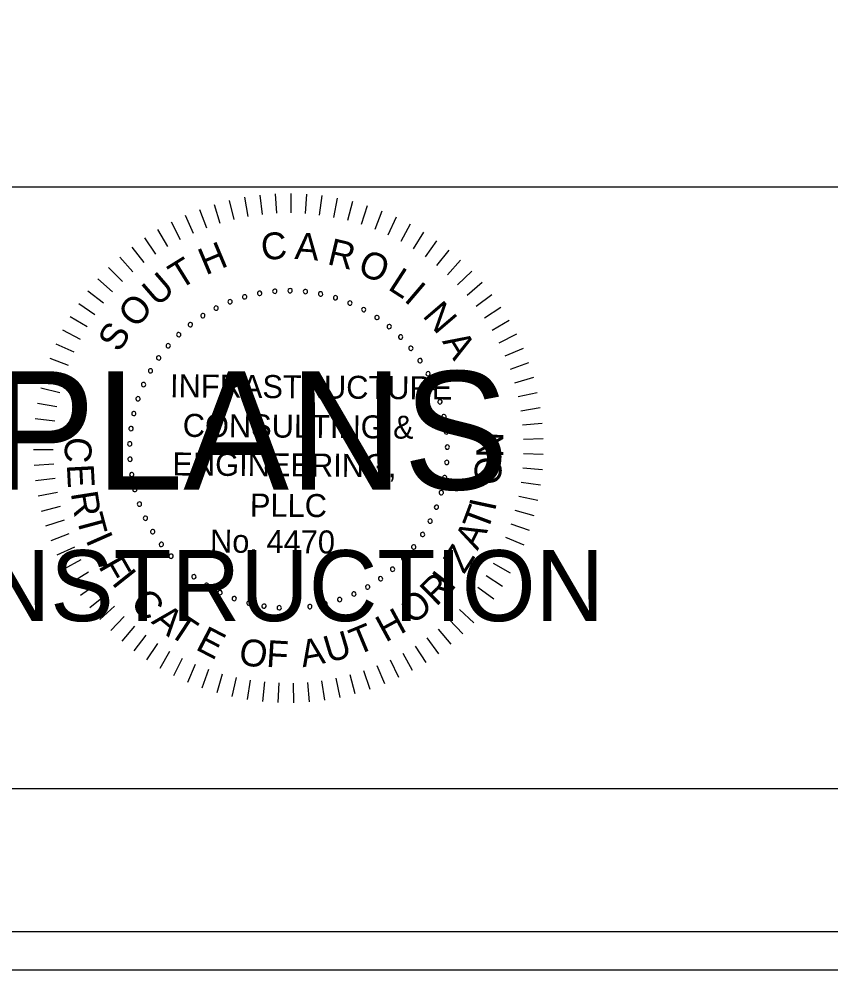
# Model space of a CAD drawing. Extents: x 967 to 1746, y 964 to 7904.
# Drawn here: x 1189.3 to 1212.88, y 6003.72 to 6031.36 of the extents above; entities that cross this region are included whole.
import ezdxf

# ---------------------------------------------------------------- set-up
doc = ezdxf.new("R2010")
doc.units = 0
for name, color, linetype in [('RD_SHT_Bndy', 7, 'Continuous'), ('RD_SHT_IplotShp', 7, 'Continuous'), ('RD_SHT_Misc1', 7, 'Continuous'), ('RD_SHT_Misc2', 7, 'Continuous'), ('RD_Sketch1', 7, 'Continuous')]:
    doc.layers.add(name, color=color, linetype=linetype)

msp = doc.modelspace()

# ---------------------------------------------------------------- linework, layer by layer
at = {"layer": 'RD_SHT_Bndy'}
for p, q in [((996.114, 6026.486), (1323.886, 6026.486)), ((1323.886, 6008.983), (996.114, 6008.983))]:
    msp.add_line(p, q, dxfattribs=at)
at = {"layer": 'RD_SHT_IplotShp'}
for points in [[(967.409, 6003.72), (1326.285, 6003.72), (1326.285, 6223.72), (967.409, 6223.72)], [(988.525, 6004.84), (1326.285, 6004.84), (1326.285, 6222.6), (988.525, 6222.6)]]:
    msp.add_lwpolyline(points, close=True, dxfattribs=at)
at = {"layer": 'RD_SHT_Misc1'}
for p, q in [((1195.403, 6026.09), (1195.536, 6025.536)), ((1195.846, 6026.181), (1195.945, 6025.62)), ((1196.292, 6026.245), (1196.357, 6025.68)), ((1196.742, 6026.282), (1196.772, 6025.714)), ((1197.194, 6026.292), (1197.189, 6025.723)), ((1197.645, 6026.274), (1197.606, 6025.706)), ((1198.094, 6026.228), (1198.02, 6025.664)), ((1198.54, 6026.156), (1198.432, 6025.596)), ((1198.98, 6026.056), (1198.838, 6025.504)), ((1194.54, 6025.827), (1194.739, 6025.293)), ((1194.968, 6025.971), (1195.134, 6025.427)), ((1199.414, 6025.929), (1199.238, 6025.387)), ((1199.839, 6025.777), (1199.63, 6025.246)), ((1194.122, 6025.656), (1194.353, 6025.136)), ((1200.253, 6025.598), (1200.013, 6025.082)), ((1193.321, 6025.241), (1193.614, 6024.752)), ((1193.715, 6025.461), (1193.978, 6024.956)), ((1200.656, 6025.395), (1200.385, 6024.894)), ((1192.94, 6024.997), (1193.263, 6024.528)), ((1201.047, 6025.167), (1200.745, 6024.684)), ((1201.422, 6024.917), (1201.092, 6024.453)), ((1192.576, 6024.731), (1192.926, 6024.282)), ((1201.781, 6024.643), (1201.424, 6024.2)), ((1192.228, 6024.443), (1192.605, 6024.016)), ((1191.899, 6024.134), (1192.301, 6023.731)), ((1202.124, 6024.349), (1201.739, 6023.928)), ((1202.447, 6024.034), (1202.038, 6023.638)), ((1191.589, 6023.805), (1192.015, 6023.428)), ((1202.751, 6023.7), (1202.318, 6023.329)), ((1191.299, 6023.459), (1191.748, 6023.108)), ((1203.034, 6023.348), (1202.579, 6023.004)), ((1191.032, 6023.095), (1191.501, 6022.772)), ((1190.787, 6022.716), (1191.274, 6022.422)), ((1203.294, 6022.979), (1202.82, 6022.664)), ((1203.532, 6022.595), (1203.04, 6022.31)), ((1190.565, 6022.323), (1191.07, 6022.059)), ((1203.746, 6022.198), (1203.237, 6021.943)), ((1190.368, 6021.916), (1190.888, 6021.684)), ((1203.936, 6021.788), (1203.412, 6021.564)), ((1190.196, 6021.499), (1190.729, 6021.299)), ((1204.1, 6021.367), (1203.563, 6021.176)), ((1190.05, 6021.072), (1190.594, 6020.905)), ((1204.238, 6020.937), (1203.691, 6020.779)), ((1189.93, 6020.636), (1190.484, 6020.503)), ((1204.349, 6020.5), (1203.794, 6020.375)), ((1189.837, 6020.195), (1190.398, 6020.095)), ((1204.434, 6020.056), (1203.872, 6019.966)), ((1189.771, 6019.748), (1190.337, 6019.683)), ((1204.491, 6019.608), (1203.925, 6019.552)), ((1189.732, 6019.298), (1190.301, 6019.267)), ((1204.522, 6019.158), (1203.953, 6019.137)), ((1189.721, 6018.847), (1190.29, 6018.851)), ((1204.524, 6018.706), (1203.955, 6018.72)), ((1189.737, 6018.396), (1190.306, 6018.434)), ((1204.499, 6018.256), (1203.932, 6018.304)), ((1189.781, 6017.946), (1190.346, 6018.019)), ((1204.447, 6017.807), (1203.884, 6017.89)), ((1189.852, 6017.5), (1190.412, 6017.608)), ((1204.367, 6017.363), (1203.81, 6017.479)), ((1189.951, 6017.06), (1190.502, 6017.201)), ((1204.261, 6016.924), (1203.712, 6017.074)), ((1190.076, 6016.626), (1190.617, 6016.8)), ((1204.128, 6016.492), (1203.589, 6016.676)), ((1190.227, 6016.2), (1190.757, 6016.408)), ((1203.969, 6016.07), (1203.442, 6016.286)), ((1190.403, 6015.785), (1190.92, 6016.024)), ((1203.784, 6015.658), (1203.271, 6015.906)), ((1190.605, 6015.381), (1191.106, 6015.651)), ((1203.574, 6015.258), (1203.078, 6015.537)), ((1190.831, 6014.99), (1191.315, 6015.291)), ((1203.341, 6014.871), (1202.862, 6015.18)), ((1191.081, 6014.614), (1191.545, 6014.943)), ((1203.085, 6014.5), (1202.626, 6014.837)), ((1191.353, 6014.253), (1191.796, 6014.61)), ((1202.806, 6014.145), (1202.368, 6014.509)), ((1191.646, 6013.91), (1192.067, 6014.293)), ((1202.506, 6013.807), (1202.092, 6014.197)), ((1191.96, 6013.585), (1192.356, 6013.994)), ((1202.186, 6013.488), (1201.796, 6013.903)), ((1192.293, 6013.28), (1192.664, 6013.712)), ((1201.847, 6013.19), (1201.484, 6013.628)), ((1192.644, 6012.996), (1192.988, 6013.45)), ((1201.491, 6012.912), (1201.155, 6013.372)), ((1193.011, 6012.734), (1193.327, 6013.208)), ((1201.119, 6012.657), (1200.811, 6013.136)), ((1193.394, 6012.495), (1193.68, 6012.987)), ((1193.791, 6012.279), (1194.047, 6012.788)), ((1200.731, 6012.425), (1200.453, 6012.922)), ((1194.2, 6012.088), (1194.424, 6012.612)), ((1199.918, 6012.034), (1199.702, 6012.561)), ((1200.331, 6012.217), (1200.083, 6012.73)), ((1194.62, 6011.923), (1194.812, 6012.459)), ((1195.05, 6011.783), (1195.208, 6012.33)), ((1195.487, 6011.67), (1195.612, 6012.225)), ((1199.063, 6011.745), (1198.913, 6012.295)), ((1199.495, 6011.877), (1199.312, 6012.416)), ((1195.93, 6011.584), (1196.021, 6012.146)), ((1196.377, 6011.524), (1196.434, 6012.091)), ((1196.828, 6011.493), (1196.85, 6012.062)), ((1197.279, 6011.488), (1197.267, 6012.058)), ((1197.73, 6011.512), (1197.683, 6012.079)), ((1198.179, 6011.562), (1198.097, 6012.126)), ((1198.624, 6011.64), (1198.508, 6012.198))]:
    msp.add_line(p, q, dxfattribs=at)
for centre, start, end in [((1195.851, 6023.285), 16.1422, 196.1422), ((1195.851, 6023.285), 196.1422, 16.1422), ((1196.285, 6023.388), 10.6038, 190.6038), ((1196.285, 6023.388), 190.6038, 10.6038), ((1196.727, 6023.447), 5.0653, 185.0653), ((1196.727, 6023.447), 185.0653, 5.0653), ((1197.172, 6023.464), 359.5268, 179.5268), ((1197.172, 6023.464), 179.5268, 359.5268), ((1197.617, 6023.438), 173.9884, 353.9884), ((1197.617, 6023.438), 353.9884, 173.9884), ((1198.057, 6023.369), 168.4499, 348.4499), ((1198.057, 6023.369), 348.4499, 168.4499), ((1198.489, 6023.258), 162.9114, 342.9114), ((1198.489, 6023.258), 342.9114, 162.9114), ((1195.023, 6022.958), 27.2191, 207.2191), ((1195.023, 6022.958), 207.2191, 27.2191), ((1195.429, 6023.142), 21.6807, 201.6807), ((1195.429, 6023.142), 201.6807, 21.6807), ((1198.908, 6023.106), 157.373, 337.373), ((1198.908, 6023.106), 337.373, 157.373), ((1194.637, 6022.736), 32.7576, 212.7576), ((1194.637, 6022.736), 212.7576, 32.7576), ((1199.31, 6022.914), 151.8345, 331.8345), ((1199.31, 6022.914), 331.8345, 151.8345), ((1199.692, 6022.684), 146.2961, 326.2961), ((1199.692, 6022.684), 326.2961, 146.2961), ((1194.274, 6022.478), 38.2961, 218.2961), ((1194.274, 6022.478), 218.2961, 38.2961), ((1200.05, 6022.419), 140.7576, 320.7576), ((1200.05, 6022.419), 320.7576, 140.7576), ((1193.937, 6022.186), 43.8345, 223.8345), ((1193.937, 6022.186), 223.8345, 43.8345), ((1200.38, 6022.12), 135.2191, 315.2191), ((1200.38, 6022.12), 315.2191, 135.2191), ((1193.63, 6021.862), 49.373, 229.373), ((1193.63, 6021.862), 229.373, 49.373), ((1200.68, 6021.79), 129.6807, 309.6807), ((1200.68, 6021.79), 309.6807, 129.6807), ((1193.356, 6021.511), 54.9114, 234.9114), ((1193.356, 6021.511), 234.9114, 54.9114), ((1200.947, 6021.433), 124.1422, 304.1422), ((1200.947, 6021.433), 304.1422, 124.1422), ((1193.117, 6021.135), 60.4499, 240.4499), ((1193.117, 6021.135), 240.4499, 60.4499), ((1201.179, 6021.052), 118.6038, 298.6038), ((1201.179, 6021.052), 298.6038, 118.6038), ((1192.915, 6020.737), 65.9884, 245.9884), ((1192.915, 6020.737), 245.9884, 65.9884), ((1201.372, 6020.651), 113.0653, 293.0653), ((1201.372, 6020.651), 293.0653, 113.0653), ((1192.753, 6020.322), 71.5268, 251.5268), ((1192.753, 6020.322), 251.5268, 71.5268), ((1201.526, 6020.233), 107.5268, 287.5268), ((1201.526, 6020.233), 287.5268, 107.5268), ((1192.632, 6019.894), 77.0653, 257.0653), ((1192.632, 6019.894), 257.0653, 77.0653), ((1201.638, 6019.801), 101.9884, 281.9884), ((1201.638, 6019.801), 281.9884, 101.9884), ((1192.552, 6019.455), 82.6038, 262.6038), ((1192.552, 6019.455), 262.6038, 82.6038), ((1201.709, 6019.361), 96.4499, 276.4499), ((1201.709, 6019.361), 276.4499, 96.4499), ((1192.515, 6019.011), 88.1422, 268.1422), ((1192.515, 6019.011), 268.1422, 88.1422), ((1201.737, 6018.917), 90.9114, 270.9114), ((1201.737, 6018.917), 270.9114, 90.9114), ((1192.522, 6018.565), 93.6807, 273.6807), ((1192.522, 6018.565), 273.6807, 93.6807), ((1201.721, 6018.471), 85.373, 265.373), ((1201.721, 6018.471), 265.373, 85.373), ((1192.571, 6018.122), 99.2191, 279.2191), ((1192.571, 6018.122), 279.2191, 99.2191), ((1201.663, 6018.029), 79.8345, 259.8345), ((1201.663, 6018.029), 259.8345, 79.8345), ((1192.662, 6017.686), 104.7576, 284.7576), ((1192.662, 6017.686), 284.7576, 104.7576), ((1201.563, 6017.595), 74.2961, 254.2961), ((1201.563, 6017.595), 254.2961, 74.2961), ((1192.796, 6017.261), 110.2961, 290.2961), ((1192.796, 6017.261), 290.2961, 110.2961), ((1201.42, 6017.173), 68.7576, 248.7576), ((1201.42, 6017.173), 248.7576, 68.7576), ((1192.97, 6016.851), 115.8345, 295.8345), ((1192.97, 6016.851), 295.8345, 115.8345), ((1201.238, 6016.766), 63.2191, 243.2191), ((1201.238, 6016.766), 243.2191, 63.2191), ((1193.182, 6016.459), 121.373, 301.373), ((1193.182, 6016.459), 301.373, 121.373), ((1201.018, 6016.379), 57.6807, 237.6807), ((1201.018, 6016.379), 237.6807, 57.6807), ((1193.432, 6016.09), 126.9114, 306.9114), ((1193.432, 6016.09), 306.9114, 126.9114), ((1200.761, 6016.014), 52.1422, 232.1422), ((1193.715, 6015.746), 312.4499, 132.4499), ((1200.761, 6016.014), 232.1422, 52.1422), ((1193.715, 6015.746), 132.4499, 312.4499), ((1200.47, 6015.677), 46.6038, 226.6038), ((1200.47, 6015.677), 226.6038, 46.6038), ((1194.031, 6015.431), 137.9884, 317.9884), ((1194.031, 6015.431), 317.9884, 137.9884), ((1200.148, 6015.369), 41.0653, 221.0653), ((1200.148, 6015.369), 221.0653, 41.0653), ((1194.376, 6015.149), 143.5268, 323.5268), ((1194.376, 6015.149), 323.5268, 143.5268), ((1199.798, 6015.093), 35.5268, 215.5268), ((1199.798, 6015.093), 215.5268, 35.5268), ((1194.746, 6014.901), 149.0653, 329.0653), ((1194.746, 6014.901), 329.0653, 149.0653), ((1195.139, 6014.69), 154.6038, 334.6038), ((1195.139, 6014.69), 334.6038, 154.6038), ((1199.026, 6014.65), 24.4499, 204.4499), ((1199.422, 6014.853), 29.9884, 209.9884), ((1199.422, 6014.853), 209.9884, 29.9884), ((1195.55, 6014.517), 160.1422, 340.1422), ((1195.55, 6014.517), 340.1422, 160.1422), ((1195.975, 6014.386), 345.6807, 165.6807), ((1198.183, 6014.363), 13.373, 193.373), ((1198.611, 6014.486), 18.9114, 198.9114), ((1198.611, 6014.486), 198.9114, 18.9114), ((1199.026, 6014.65), 204.4499, 24.4499), ((1195.975, 6014.386), 165.6807, 345.6807), ((1196.412, 6014.295), 171.2191, 351.2191), ((1196.412, 6014.295), 351.2191, 171.2191), ((1196.855, 6014.248), 356.7576, 176.7576), ((1196.855, 6014.248), 176.7576, 356.7576), ((1197.301, 6014.243), 2.2961, 182.2961), ((1197.301, 6014.243), 182.2961, 2.2961), ((1197.745, 6014.282), 7.8345, 187.8345), ((1197.745, 6014.282), 187.8345, 7.8345), ((1198.183, 6014.363), 193.373, 13.373)]:
    msp.add_arc(centre, 0.0627, start, end, dxfattribs=at)
at = {"layer": 'RD_Sketch1'}
msp.add_lwpolyline([(967.409, 6003.72), (1326.285, 6003.72), (1326.285, 6223.72), (967.409, 6223.72)], close=True, dxfattribs=at)

# ---------------------------------------------------------------- texts
at = {"layer": 'RD_SHT_Misc1'}
for s, height, rotation, p in [('C', 0.78, 4.7281, (1196.355, 6024.346)), ('A', 0.78, 355.6981, (1197.29, 6024.39)), ('R', 0.78, 346.6681, (1198.222, 6024.238)), ('H', 0.78, 22.7882, (1194.72, 6023.904)), ('T', 0.78, 31.8182, (1193.961, 6023.478)), ('O', 0.78, 337.638, (1199.096, 6023.972)), ('L', 0.78, 327.108, (1199.981, 6023.52)), ('U', 0.78, 40.8482, (1193.306, 6022.976)), ('I', 0.78, 319.578, (1200.451, 6023.182)), ('O', 0.78, 49.8782, (1192.707, 6022.341)), ('N', 0.78, 310.548, (1200.994, 6022.728)), ('S', 0.78, 58.9083, (1192.211, 6021.642)), ('A', 0.78, 301.5179, (1201.576, 6021.991)), ('INFRASTRUCTURE', 0.66873, 359.5268, (1193.682, 6020.367)), ('CONSULTING &', 0.66873, 359.5268, (1194.051, 6019.217)), ('C', 0.78, 267.025, (1190.646, 6019.227)), ('N', 0.78, 89.2085, (1203.359, 6018.604)), ('ENGINEERING,', 0.66873, 359.5268, (1193.751, 6018.095)), ('O', 0.78, 83.2085, (1203.26, 6017.786)), ('E', 0.78, 273.025, (1190.685, 6018.408)), ('R', 0.78, 279.025, (1190.799, 6017.583)), ('PLLC', 0.6687, 359.5268, (1196.002, 6016.9)), ('T', 0.78, 69.3954, (1202.891, 6016.428)), ('I', 0.78, 77.9093, (1203.121, 6017.032)), ('T', 0.78, 285.025, (1190.955, 6016.878)), ('I', 0.78, 293.7713, (1191.221, 6016.225)), ('No. 4470', 0.6687, 359.5268, (1194.843, 6015.855)), ('A', 0.78, 63.3954, (1202.616, 6015.888)), ('Z', 0.78, 57.3954, (1202.224, 6015.206)), ('F', 0.78, 299.7713, (1191.589, 6015.455)), ('I', 0.78, 308.5268, (1191.965, 6014.973)), ('I', 0.78, 52.3339, (1201.856, 6014.69)), ('R', 0.78, 44.5268, (1201.415, 6014.267)), ('C', 0.78, 314.5268, (1192.496, 6014.346)), ('O', 0.78, 38.5268, (1200.73, 6013.731)), ('A', 0.78, 320.5268, (1193.115, 6013.822)), ('H', 0.78, 28.5268, (1199.942, 6013.23)), ('T', 0.78, 326.5268, (1193.602, 6013.478)), ('E', 0.78, 332.5268, (1194.394, 6013.051)), ('T', 0.78, 22.5268, (1199.108, 6012.856)), ('O', 0.78, 350.5268, (1195.647, 6012.614)), ('A', 0.78, 10.5268, (1197.537, 6012.517)), ('U', 0.78, 16.5268, (1198.288, 6012.638)), ('F', 0.78, 356.5268, (1196.465, 6012.532))]:
    msp.add_text(s, height=height, rotation=rotation, dxfattribs=at).set_placement(p)
at = {"layer": 'RD_SHT_Misc2'}
for s, height, p in [('FINAL PLANS', 3.4375, (1174.145, 6017.685)), ('NOT FOR CONSTRUCTION', 2.0625, (1170.901, 6013.86))]:
    msp.add_text(s, height=height, dxfattribs=at).set_placement(p)

doc.saveas('drawing.dxf')
